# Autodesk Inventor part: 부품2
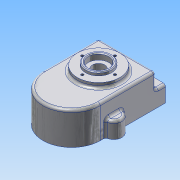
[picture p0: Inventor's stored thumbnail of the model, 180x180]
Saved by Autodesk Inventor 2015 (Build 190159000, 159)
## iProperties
Created: 2024-03
Part Number: 부품2
Material: 알루미늄 6061
Document SubType Name: Modeling
Designer: 학생용
Density: 2.7 g/cm^3
Appearance: 알루미늄 - 평지
Author: 학생용
## Parameters: d1 = 68 mm, d4 = 0, d5 = 52 mm, d6 = 35 mm, d7 = 6 mm, d8 = 0, d9 = 32 mm, d10 = 4 mm, d11 = 0, d12 = 12 mm, d13 = 12 mm, d17 = 0, d20 = 63.5 mm, d21 = 63.5 mm, d23 = 0, d24 = 3 mm, d25 = 36 mm, d26 = 36 mm, d27 = 33 mm, d28 = 35 mm, d29 = 28 mm, d31 = 0, d33 = 21 mm, d34 = 3.242 mm, d35 = 8 mm, d36 = 3.023 mm, d37 = 2 mm, d38 = 82 deg, d40 = 118 deg, d42 = 360 deg, d51 = 7.3 mm, d53 = 25 mm, d54 = 15 mm, d55 = 90 deg, d58 = 0, d60 = 7 mm, d61 = 120 deg, d62 = 90 deg, d68 = 1 mm, d69 = 2 mm, d70 = 45 deg, d71 = 1 mm, d72 = 2 mm, d73 = 45 deg, d74 = 1 mm, d75 = 2 mm, d76 = 45 deg, d77 = 4 mm, d78 = 26 mm, d79 = 4 mm, d80 = 4 mm, d81 = 63.5 mm, d82 = 63.5 mm, d83 = 4 mm, d84 = 26.5 mm, d85 = 4.134 mm, d87 = 3.023 mm, d88 = 2 mm, d89 = 82 deg, d90 = 12 mm, d91 = 118 deg, d92 = 3 mm, d93 = 3 mm, d94 = 3 mm, d95 = 3 mm, d98 = 3 mm, d99 = 3 mm, d100 = 3 mm, d101 = 3 mm, d140 = 0.5 mm, d141 = 0, d143 = 63.5 mm, d144 = 6 mm, d146 = 11 mm, d147 = 0, d148 = 90 deg, d149 = 0, d150 = 0, d151 = 8 mm, d154 = 10.5 mm, d155 = 11 mm, d156 = 0.62479 mm, d157 = 10.589 mm, d158 = 3.023 mm, d159 = 2 mm, d160 = 82 deg, d161 = 16 mm, d162 = 118 deg, d165 = 10.5 mm, d166 = 11 mm, d167 = 0.62479 mm, d168 = 10.589 mm, d169 = 3.023 mm, d170 = 2 mm, d171 = 82 deg, d172 = 16 mm, d173 = 118 deg
